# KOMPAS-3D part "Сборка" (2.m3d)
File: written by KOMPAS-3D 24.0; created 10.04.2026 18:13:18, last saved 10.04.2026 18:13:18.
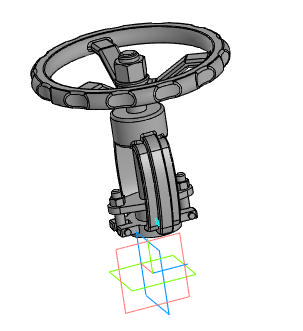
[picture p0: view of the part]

Document properties: Автор: R2D2; Полное имя файла: E:\Работа\Зайцев\VSO3131M-F-S Клапан запорный DN.ru Ду15-100 Ру16\DN20\исходные материалы\2.m3d

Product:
- Body: Тело 2  | qty 1
    Масса: 1.428573
- Part/product: Сборка
    Масса: 1.44705

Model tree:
1. Операция без истории:1
2. Эскиз:1  (with: Грань.Операция без истории:1, Ребро.Операция без истории:1)
3. Элемент выдавливания:1
     Расстояние 2 = 4
4. Эскиз:2  (with: Грань.Операция без истории:1, Ребро.Операция без истории:1)
5. Элемент выдавливания:2  (with: Грань.Операция без истории:1)
     Расстояние 1 = -26.625; Смещение 1 = 2; Расстояние 2 = -2
6. Средняя плоскость:1  (with: Грань.Операция без истории:1)
7. Зеркальный массив:1
8. Экземпляр ( 1 )
9. Экземпляр ( 2 )  (with: Элемент выдавливания:2)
